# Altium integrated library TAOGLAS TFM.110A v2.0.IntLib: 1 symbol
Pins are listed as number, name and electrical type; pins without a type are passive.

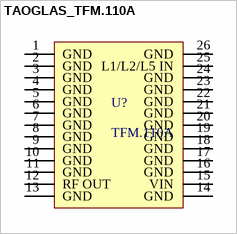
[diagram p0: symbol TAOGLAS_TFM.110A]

## TAOGLAS_TFM.110A
designator U?, comment TFM.110A
Surface Mount GNSS Front End Active Electronics. Covering the full Multiband GNSS Spectrum excluding the L-Bands; ComponentLibStatus: Created; MFG: Taoglas; Temp_High: +85C; Temp_Low: -40C
footprint TAOGLAS_TFM.110A (Surface Mount GNSS Front End Active Electronics. Covering the full Multiband GNSS Spectrum excluding the L-Bands)
pins: 1 GND, 2 GND, 3 GND, 4 GND, 5 GND, 6 GND, 7 GND, 8 GND, 9 GND, 10 GND, 11 GND, 12 RF OUT, 13 GND, 14 GND, 15 VIN, 16 GND, 17 GND, 18 GND, 19 GND, 20 GND, 21 GND, 22 GND, 23 GND, 24 GND, 25 L1/L2/L5 IN, 26 GND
